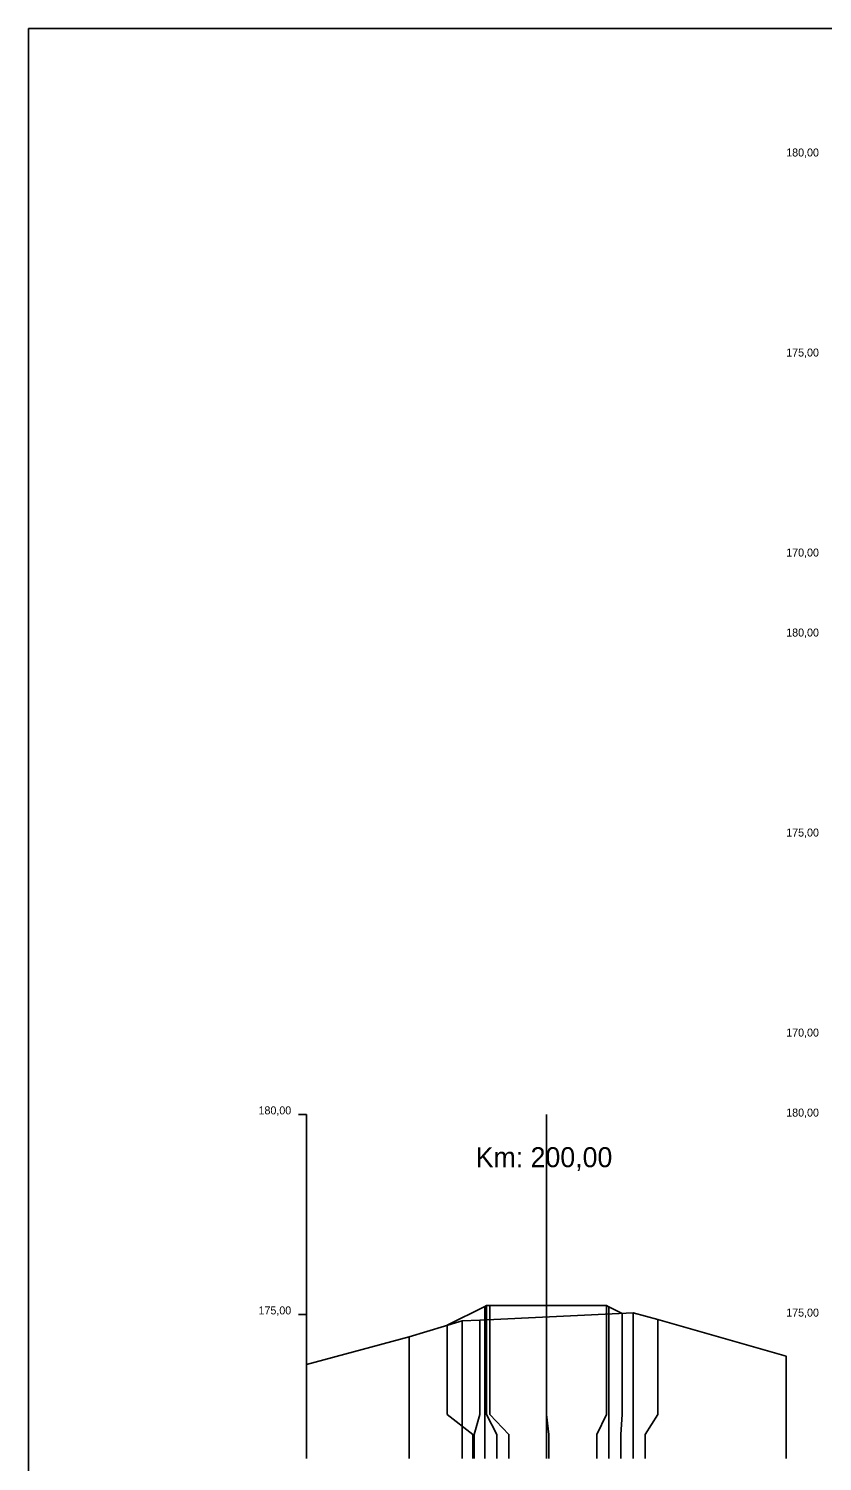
# Model space of a CAD drawing. Extents: x -614174 to -599765, y -1185887 to -1181080.
# Drawn here: x -608814.98 to -608795.12, y -1184489.11 to -1184453.29 of the extents above; entities that cross this region are included whole.
import ezdxf

# ---------------------------------------------------------------- set-up
doc = ezdxf.new("R2010")
doc.units = 0
for name, color, linetype in [('11', 7, 'Continuous'), ('16', 7, 'Continuous'), ('21', 7, 'Continuous'), ('28', 7, 'Continuous'), ('8', 7, 'Continuous'), ('návrh', 7, 'Continuous')]:
    doc.layers.add(name, color=color, linetype=linetype)

msp = doc.modelspace()

# ---------------------------------------------------------------- linework, layer by layer
for points in [[(-608808.025, -1184486.685), (-608805.46, -1184485.993), (-608804.133, -1184485.591), (-608803.693, -1184485.579), (-608799.853, -1184485.396), (-608799.239, -1184485.561), (-608796.025, -1184486.479)], [(-608804.505, -1184485.704), (-608803.563, -1184485.233), (-608803.522, -1184485.213), (-608803.441, -1184485.213), (-608802.023, -1184485.213), (-608800.523, -1184485.213), (-608800.464, -1184485.242), (-608800.13, -1184485.409)], [(-608803.522, -1184485.213), (-608803.522, -1184485.213), (-608803.522, -1184485.213)], [(-608802.023, -1184485.213), (-608802.023, -1184485.213), (-608802.023, -1184485.213)], [(-608800.523, -1184485.213), (-608800.523, -1184485.213), (-608800.523, -1184485.213)], [(-608804.505, -1184485.704), (-608804.505, -1184485.704), (-608804.505, -1184485.704)]]:
    msp.add_lwpolyline(points)
at = {"layer": '11'}
for points in [[(-608803.563, -1184485.233), (-608803.563, -1184487.932), (-608803.563, -1184488.432), (-608803.563, -1184489.033)], [(-608803.522, -1184485.213), (-608803.522, -1184487.932), (-608803.263, -1184488.432), (-608803.263, -1184489.033)], [(-608803.441, -1184485.213), (-608803.441, -1184487.932), (-608802.963, -1184488.432), (-608802.963, -1184489.033)], [(-608802.023, -1184485.213), (-608802.023, -1184487.932), (-608801.963, -1184488.432), (-608801.963, -1184489.033)], [(-608800.523, -1184485.213), (-608800.523, -1184487.932), (-608800.764, -1184488.432), (-608800.764, -1184489.033)], [(-608800.464, -1184485.242), (-608800.464, -1184487.932), (-608800.464, -1184488.432), (-608800.464, -1184489.033)], [(-608800.13, -1184485.409), (-608800.13, -1184487.932), (-608800.164, -1184488.432), (-608800.164, -1184489.033)], [(-608799.853, -1184485.396), (-608799.853, -1184487.932), (-608799.853, -1184488.432), (-608799.853, -1184489.033)], [(-608804.505, -1184485.704), (-608804.505, -1184487.932), (-608803.863, -1184488.432), (-608803.863, -1184489.033)], [(-608804.133, -1184485.591), (-608804.133, -1184487.932), (-608804.133, -1184488.432), (-608804.133, -1184489.033)], [(-608803.693, -1184485.579), (-608803.693, -1184487.932), (-608803.833, -1184488.432), (-608803.833, -1184489.033)], [(-608799.239, -1184485.561), (-608799.239, -1184487.932), (-608799.553, -1184488.432), (-608799.553, -1184489.033)], [(-608805.46, -1184485.993), (-608805.46, -1184487.932), (-608805.46, -1184488.432), (-608805.46, -1184489.033)], [(-608796.025, -1184486.479), (-608796.025, -1184487.932), (-608796.025, -1184488.432), (-608796.025, -1184489.033)], [(-608808.025, -1184486.685), (-608808.025, -1184487.932), (-608808.025, -1184488.432), (-608808.025, -1184489.033)]]:
    msp.add_lwpolyline(points, dxfattribs=at)
at = {"layer": '16'}
msp.add_lwpolyline([(-608800.13, -1184485.409), (-608800.13, -1184485.409), (-608800.131, -1184485.409)], dxfattribs=at)
at = {"layer": '21'}
for p, q in [((-608808.225, -1184480.432), (-608808.025, -1184480.432)), ((-608808.225, -1184485.432), (-608808.025, -1184485.432))]:
    msp.add_line(p, q, dxfattribs=at)
at = {"layer": '28'}
msp.add_line((-608802.025, -1184489.033), (-608802.025, -1184480.432), dxfattribs=at)
at = {"layer": '8'}
msp.add_line((-608808.025, -1184489.033), (-608808.025, -1184480.432), dxfattribs=at)
at = {"layer": 'návrh'}
for p, q in [((-608814.975, -1184519.11), (-608814.975, -1184453.291)), ((-608814.975, -1184453.291), (-608730.975, -1184453.291))]:
    msp.add_line(p, q, dxfattribs=at)

# ---------------------------------------------------------------- texts
at = {"layer": '21'}
for s, p in [('180,00', (-608796.025, -1184456.487)), ('175,00', (-608796.025, -1184461.487)), ('170,00', (-608796.025, -1184466.487)), ('180,00', (-608796.025, -1184468.487)), ('175,00', (-608796.025, -1184473.487)), ('170,00', (-608796.025, -1184478.487)), ('180,00', (-608809.225, -1184480.432)), ('180,00', (-608796.025, -1184480.487)), ('175,00', (-608809.225, -1184485.432)), ('175,00', (-608796.025, -1184485.487))]:
    msp.add_text(s, height=0.2, dxfattribs=at).set_placement(p)
at = {"layer": '28'}
msp.add_text('Km: 200,00', height=0.5, dxfattribs=at).set_placement((-608803.794, -1184481.752))

doc.saveas('drawing.dxf')
